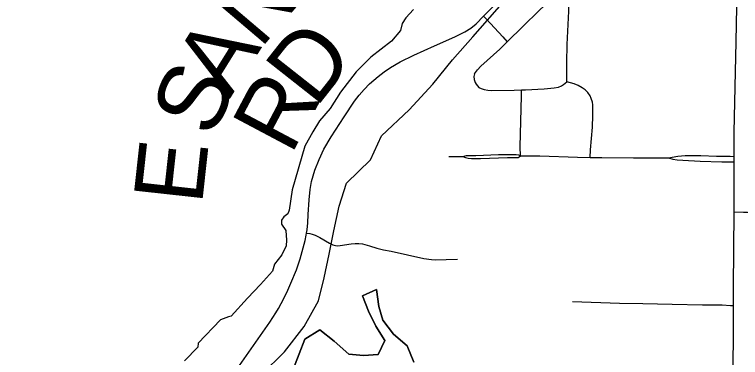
# Model space of a CAD drawing. Extents: x 63.4 to 97.4, y 0.4 to 22.4.
# Drawn here: x 66.854 to 67.452, y 17.746 to 18.029 of the extents above; entities that cross this region are included whole.
import ezdxf

# ---------------------------------------------------------------- set-up
doc = ezdxf.new("R2010")
doc.units = 0
for name, color, linetype in [('GM_X_County_Road', 7, 'Continuous'), ('GM_X_Major_Lake', 7, 'Continuous'), ('GM_X_Minor_River', 7, 'Continuous'), ('GM_X_Township_Road', 7, 'Continuous'), ('GM_X_Township_Road_Text', 7, 'Continuous'), ('SH_Cut_Line', 7, 'Continuous')]:
    doc.layers.add(name, color=color, linetype=linetype)

msp = doc.modelspace()

# ---------------------------------------------------------------- linework, layer by layer
at = {"layer": 'GM_X_County_Road'}
for points in [[(67.44665, 17.90764), (67.44664, 17.91219), (67.44662, 17.93215), (67.44827, 18.00667), (67.44927, 18.0501), (67.44913, 18.05926), (67.44829, 18.07095), (67.44625, 18.0855), (67.44501, 18.09215)], [(67.18244, 18.03329), (67.17619, 18.02651), (67.17306, 18.02165), (67.17167, 18.01591), (67.16437, 18.00705), (67.14717, 17.99402), (67.13518, 17.98185), (67.12231, 17.96517), (67.1138, 17.95161), (67.1049, 17.94148), (67.09937, 17.93249), (67.09294, 17.92051), (67.08251, 17.88453), (67.07991, 17.86785), (67.07887, 17.86489), (67.07556, 17.86228), (67.07348, 17.85951), (67.07365, 17.85638), (67.07713, 17.85116), (67.07765, 17.84317), (67.07747, 17.83847), (67.074, 17.83118), (67.06792, 17.82336), (67.06618, 17.81762), (67.05627, 17.8065), (67.04567, 17.79538), (67.03211, 17.78043), (67.02986, 17.78008), (67.02325, 17.77747), (67.005, 17.75836), (67.00465, 17.75508), (66.99353, 17.74376)], [(67.44661, 17.86654), (67.44668, 17.87649), (67.44665, 17.90764)], [(67.44616, 17.78922), (67.44625, 17.80436), (67.44661, 17.86654)], [(67.44581, 17.7314), (67.44606, 17.77343), (67.44616, 17.78922)]]:
    msp.add_lwpolyline(points, dxfattribs=at)
at = {"layer": 'GM_X_Major_Lake'}
msp.add_lwpolyline([(67.05705, 17.73237), (67.07603, 17.75099), (67.09234, 17.77188), (67.1041, 17.79316), (67.10866, 17.81215), (67.11283, 17.83153), (67.11662, 17.8509), (67.12117, 17.87103), (67.12724, 17.89003), (67.14697, 17.9094), (67.15608, 17.92916), (67.17885, 17.95044), (67.1982, 17.97171), (67.21452, 17.99184), (67.23121, 18.01084), (67.25739, 18.04048)], dxfattribs=at)
at = {"layer": 'GM_X_Minor_River'}
for points in [[(67.18266, 17.74266), (67.17728, 17.75594), (67.16584, 17.76577), (67.15705, 17.77713), (67.15395, 17.78852), (67.15198, 17.80257), (67.14024, 17.79719), (67.14524, 17.78468), (67.15138, 17.77216), (67.15865, 17.76041), (67.15339, 17.74898), (67.14125, 17.74817), (67.12909, 17.74925), (67.11689, 17.75984), (67.10507, 17.76928), (67.09296, 17.76163), (67.08809, 17.74944), (67.08284, 17.73611)], [(67.08284, 17.73611), (67.08809, 17.74944), (67.09296, 17.76163), (67.10507, 17.76928), (67.11689, 17.75984), (67.12909, 17.74925), (67.14125, 17.74817), (67.15339, 17.74898), (67.15865, 17.76041), (67.15138, 17.77216), (67.14524, 17.78468), (67.14024, 17.79719), (67.15198, 17.80257), (67.15395, 17.78852), (67.15705, 17.77713), (67.16584, 17.76577), (67.17728, 17.75594), (67.18266, 17.74266)]]:
    msp.add_lwpolyline(points, dxfattribs=at)
at = {"layer": 'GM_X_Township_Road'}
msp.add_line((67.21151, 17.91205), (67.22297, 17.91216), dxfattribs=at)
for points in [[(67.24012, 18.02781), (67.25154, 18.03938), (67.2591, 18.04649), (67.26758, 18.05285), (67.27907, 18.06178), (67.32008, 18.09219), (67.35094, 18.11596), (67.36213, 18.12367), (67.37333, 18.13079), (67.38861, 18.13881), (67.40707, 18.14759), (67.41476, 18.15127), (67.41973, 18.15425), (67.42263, 18.15616), (67.42487, 18.15773), (67.42892, 18.16121)], [(67.25969, 18.00673), (67.27276, 18.01965), (67.28561, 18.03229), (67.2907, 18.03675), (67.30355, 18.046)], [(67.30888, 17.97377), (67.30866, 17.98163), (67.30866, 17.9896), (67.30917, 18.00441), (67.31033, 18.03197), (67.31031, 18.03595)], [(67.09427, 17.84895), (67.09476, 17.85176), (67.09524, 17.85748), (67.09563, 17.86425), (67.09639, 17.87628), (67.09723, 17.88499), (67.09832, 17.89153), (67.1011, 17.90085), (67.10461, 17.90969), (67.10848, 17.91816), (67.11447, 17.92845), (67.12523, 17.94476), (67.13385, 17.95774), (67.13764, 17.96273), (67.14178, 17.96745), (67.14619, 17.97191), (67.15322, 17.97812), (67.15816, 17.98198), (67.16336, 17.9855), (67.17128, 17.99012), (67.18267, 17.99568), (67.19968, 18.00338), (67.21653, 18.01083), (67.22466, 18.01497), (67.22956, 18.01799), (67.23399, 18.02136), (67.24012, 18.02781)], [(67.24012, 18.02781), (67.24228, 18.02549), (67.25598, 18.01073), (67.25969, 18.00673)], [(67.23257, 17.98018), (67.23516, 17.98354), (67.23782, 17.98651), (67.25343, 18.00053), (67.25969, 18.00673)], [(67.23257, 17.98018), (67.23209, 17.97801), (67.23229, 17.97549), (67.23315, 17.97313), (67.234, 17.97172), (67.23506, 17.97037), (67.23634, 17.96909), (67.23822, 17.96804), (67.24069, 17.96729), (67.2437, 17.96677), (67.24677, 17.96658), (67.2653, 17.96689), (67.27138, 17.96692)], [(67.27138, 17.96692), (67.27462, 17.96694), (67.29007, 17.96775), (67.29836, 17.96868), (67.30197, 17.96931), (67.30431, 17.97027), (67.306, 17.97154), (67.30888, 17.97377)], [(67.32787, 17.91137), (67.32836, 17.9176), (67.32983, 17.93636), (67.33016, 17.94587), (67.33006, 17.95209), (67.33012, 17.95466), (67.3298, 17.95679), (67.32895, 17.95987), (67.32786, 17.96209), (67.32614, 17.96473), (67.32394, 17.96699), (67.32135, 17.96878), (67.31822, 17.97049), (67.31472, 17.97187), (67.30888, 17.97377)], [(67.2705, 17.91256), (67.27041, 17.92012), (67.27128, 17.96209), (67.27138, 17.96692)], [(67.22297, 17.91216), (67.22597, 17.91285), (67.22817, 17.91306), (67.23067, 17.91306), (67.23377, 17.91306), (67.25248, 17.91366), (67.26019, 17.91376), (67.26379, 17.91376), (67.26689, 17.91376), (67.26884, 17.91343), (67.2705, 17.91256)], [(67.22297, 17.91216), (67.22517, 17.91126), (67.22747, 17.91085), (67.23017, 17.91056), (67.23752, 17.91048), (67.25987, 17.91123), (67.26498, 17.91123), (67.26798, 17.91123), (67.26871, 17.91136), (67.26944, 17.9117), (67.2705, 17.91256)], [(67.2705, 17.91256), (67.28655, 17.91262), (67.31769, 17.91149), (67.32787, 17.91137)], [(67.32787, 17.91137), (67.3377, 17.91125), (67.36359, 17.91113), (67.3926, 17.911)], [(67.3926, 17.911), (67.40035, 17.91251), (67.40623, 17.91304), (67.41911, 17.91301), (67.43212, 17.91251), (67.44337, 17.91226), (67.44664, 17.91219)], [(67.3926, 17.911), (67.39623, 17.91), (67.39973, 17.90938), (67.40436, 17.90913), (67.41874, 17.90838), (67.4365, 17.90764), (67.44337, 17.90764), (67.44665, 17.90764)], [(67.44661, 17.86654), (67.45446, 17.86635), (67.45758, 17.86627), (67.51358, 17.86561), (67.51979, 17.86584), (67.52598, 17.86654), (67.53205, 17.86785), (67.53794, 17.86984), (67.54078, 17.87111), (67.54621, 17.87413), (67.55138, 17.87759), (67.55634, 17.88136), (67.56802, 17.89162), (67.57706, 17.89895)], [(66.84555, 17.52549), (66.85736, 17.53548), (66.88252, 17.55869), (66.96142, 17.63604), (66.96996, 17.64501), (66.97993, 17.65727), (66.99973, 17.68447), (67.01154, 17.70086), (67.02422, 17.7188), (67.03718, 17.73718), (67.06395, 17.77564), (67.06893, 17.78319), (67.07107, 17.78675), (67.07335, 17.79102), (67.07791, 17.8), (67.08132, 17.80769), (67.08602, 17.81866), (67.08901, 17.82778), (67.09311, 17.84277), (67.09396, 17.84721), (67.09427, 17.84895)], [(67.09427, 17.84895), (67.09707, 17.84856), (67.09882, 17.84816), (67.10137, 17.84721), (67.10526, 17.84541), (67.11316, 17.8406), (67.11597, 17.83935), (67.11818, 17.83869), (67.12017, 17.83853), (67.12199, 17.83869), (67.13113, 17.84017), (67.1342, 17.84052), (67.13726, 17.84047), (67.1403, 17.84014), (67.14622, 17.83849), (67.15209, 17.83657), (67.15769, 17.83518), (67.16406, 17.83399), (67.19104, 17.82801), (67.19712, 17.82718), (67.20019, 17.82696), (67.20943, 17.82716), (67.21867, 17.82755)], [(67.31349, 17.79262), (67.35204, 17.79131), (67.37132, 17.79092), (67.39555, 17.7904), (67.42065, 17.78976), (67.43677, 17.78976), (67.44371, 17.78936), (67.44616, 17.78922)]]:
    msp.add_lwpolyline(points, dxfattribs=at)
at = {"layer": 'SH_Cut_Line'}
msp.add_lwpolyline([(67.18244, 18.03329), (67.17619, 18.02651), (67.17306, 18.02165), (67.17167, 18.01591), (67.16437, 18.00705), (67.14717, 17.99402), (67.13518, 17.98185), (67.12231, 17.96517), (67.1138, 17.95161), (67.1049, 17.94148), (67.09937, 17.93249), (67.09294, 17.92051), (67.08251, 17.88453), (67.07991, 17.86785), (67.07887, 17.86489), (67.07556, 17.86228), (67.07348, 17.85951), (67.07365, 17.85638), (67.07713, 17.85116), (67.07765, 17.84317), (67.07747, 17.83847), (67.074, 17.83118), (67.06792, 17.82336), (67.06618, 17.81762), (67.05627, 17.8065), (67.04567, 17.79538), (67.03211, 17.78043), (67.02986, 17.78008), (67.02325, 17.77747), (67.005, 17.75836), (67.00465, 17.75508), (66.99353, 17.74376)], dxfattribs=at)

# ---------------------------------------------------------------- texts
at = {"layer": 'GM_X_Township_Road_Text'}
for s, rotation, p in [('N', 49.66502, (67.05608, 18.00011)), ('D', 51.76461, (67.10176, 17.95131)), ('A', 58.11663, (67.03098, 17.95944)), ('S', 66.94739, (67.01703, 17.92622)), ('R', 62.05149, (67.08136, 17.91234)), ('E', 83.73907, (67.00803, 17.8716))]:
    msp.add_text(s, height=0.05682, rotation=rotation, dxfattribs=at).set_placement(p)

doc.saveas('drawing.dxf')
